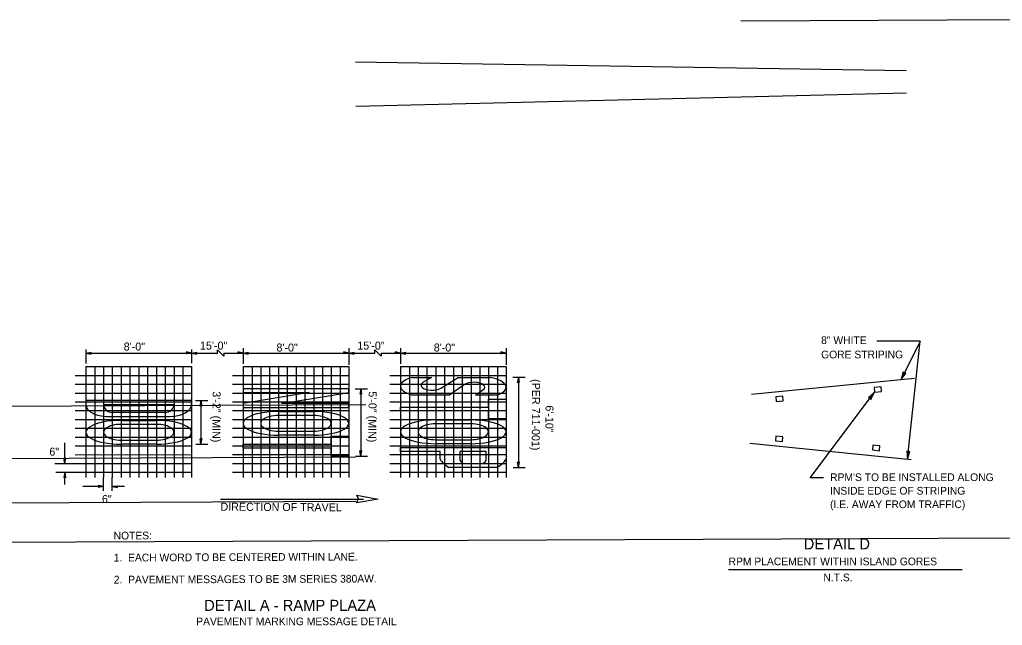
# Model space of a CAD drawing. Extents: x 583689 to 590775, y 1496016 to 1497365.
# Drawn here: x 587294 to 588186, y 1496787 to 1497337 of the extents above; entities that cross this region are included whole.
import ezdxf

# ---------------------------------------------------------------- set-up
doc = ezdxf.new("R2010")
doc.units = 0
for name, color, linetype in [('1', 7, 'Continuous'), ('12', 7, 'Continuous'), ('20', 7, 'Continuous'), ('21', 7, 'Continuous'), ('32', 7, 'Continuous'), ('5', 7, 'Continuous'), ('50', 7, 'Continuous'), ('52', 7, 'Continuous'), ('PavtMessage', 7, 'Continuous'), ('TextNotes', 7, 'Continuous')]:
    doc.layers.add(name, color=color, linetype=linetype)

msp = doc.modelspace()

# ---------------------------------------------------------------- linework, layer by layer
at = {"layer": '1'}
for points in [[(588075.82, 1497003.36), (588069.51, 1497002.74), (588069.93, 1496998.47), (588076.24, 1496999.09)], [(587986.62, 1496994.95), (587980.31, 1496994.33), (587980.73, 1496990.06), (587987.04, 1496990.68)], [(587986.66, 1496957.79), (587980.34, 1496958.42), (587979.91, 1496954.15), (587986.23, 1496953.52)], [(588074.73, 1496949.55), (588068.41, 1496950.18), (588067.98, 1496945.91), (588074.3, 1496945.28)]]:
    msp.add_lwpolyline(points, close=True, dxfattribs=at)
at = {"layer": '12'}
for p, q in [((588106.1, 1497011), (587958.1, 1496996.48)), ((587956.6, 1496952.04), (588103.15, 1496937.28))]:
    msp.add_line(p, q, dxfattribs=at)
at = {"layer": '20'}
for p, q in [((587599.7, 1496898.06), (587601.24, 1496901.44)), ((587619.12, 1496901.14), (587599.7, 1496898.06)), ((587599.82, 1496904.89), (587619.12, 1496901.14)), ((587601.24, 1496901.44), (587599.82, 1496904.89))]:
    msp.add_line(p, q, dxfattribs=at)
at = {"layer": '21'}
for p, q in [((587353.86, 1497037.2), (587353.86, 1497024.45)), ((587353.86, 1497034.01), (587358.71, 1497034.78)), ((587353.86, 1497034.01), (587358.51, 1497034.34)), ((587353.86, 1497034.01), (587449.86, 1497034.01)), ((587353.86, 1497034.01), (587358.68, 1497033.07)), ((587353.86, 1497034.01), (587358.5, 1497033.52)), ((587358.33, 1497033.93), (587358.71, 1497034.78)), ((587358.68, 1497033.07), (587358.33, 1497033.93)), ((587445.39, 1497034.09), (587445, 1497033.24)), ((587449.86, 1497034.01), (587445, 1497033.24)), ((587449.86, 1497034.01), (587445.03, 1497034.95)), ((587445.03, 1497034.95), (587445.39, 1497034.09)), ((587449.86, 1497034.01), (587445.21, 1497033.68)), ((587449.86, 1497034.01), (587445.22, 1497034.49)), ((587449.86, 1497037.2), (587449.86, 1497024.75)), ((587449.86, 1497034.01), (587454.71, 1497034.78)), ((587449.86, 1497034.01), (587454.51, 1497034.33)), ((587449.86, 1497034.01), (587454.68, 1497033.07)), ((587449.86, 1497034.01), (587454.5, 1497033.52)), ((587449.86, 1497034.01), (587473.28, 1497034.01)), ((587454.33, 1497033.93), (587454.71, 1497034.78)), ((587454.68, 1497033.07), (587454.33, 1497033.93)), ((587473.28, 1497034.01), (587473.27, 1497036.99)), ((587473.27, 1497036.99), (587479.04, 1497031.02)), ((587479.04, 1497034.01), (587479.04, 1497031.02)), ((587479.04, 1497034.01), (587496.7, 1497034.01)), ((587492.23, 1497034.09), (587491.84, 1497033.24)), ((587496.7, 1497034.01), (587491.84, 1497033.24)), ((587496.7, 1497034.01), (587491.87, 1497034.95)), ((587491.87, 1497034.95), (587492.23, 1497034.09)), ((587496.7, 1497034.01), (587492.05, 1497034.49)), ((587496.7, 1497034.01), (587492.05, 1497033.69)), ((587496.7, 1497038.33), (587496.69, 1497024.31)), ((587496.7, 1497034.01), (587501.55, 1497034.78)), ((587496.7, 1497034.01), (587501.35, 1497034.34)), ((587496.7, 1497034.01), (587592.45, 1497034.01)), ((587496.7, 1497034.01), (587501.52, 1497033.07)), ((587496.7, 1497034.01), (587501.34, 1497033.53)), ((587501.17, 1497033.93), (587501.55, 1497034.78)), ((587501.52, 1497033.07), (587501.17, 1497033.93)), ((587587.97, 1497034.09), (587587.59, 1497033.24)), ((587592.45, 1497034.01), (587587.59, 1497033.24)), ((587592.45, 1497034.01), (587587.62, 1497034.95)), ((587587.62, 1497034.95), (587587.97, 1497034.09)), ((587592.45, 1497034.01), (587587.79, 1497033.68)), ((587592.45, 1497034.01), (587587.8, 1497034.49)), ((587592.7, 1497038.34), (587592.7, 1497023.26)), ((587592.7, 1497035.72), (587592.7, 1497023.26)), ((587592.7, 1497034.01), (587597.55, 1497034.78)), ((587592.7, 1497034.01), (587597.34, 1497034.33)), ((587592.7, 1497034.01), (587616.12, 1497034.01)), ((587592.7, 1497034.01), (587597.52, 1497033.07)), ((587592.7, 1497034.01), (587597.34, 1497033.52)), ((587597.17, 1497033.93), (587597.55, 1497034.78)), ((587597.52, 1497033.07), (587597.17, 1497033.93)), ((587616.12, 1497034.01), (587616.11, 1497036.99)), ((587616.11, 1497036.99), (587621.88, 1497031.02)), ((587621.88, 1497034.01), (587621.88, 1497031.02)), ((587621.88, 1497034.01), (587639.53, 1497034.01)), ((587635.06, 1497034.09), (587634.68, 1497033.24)), ((587639.53, 1497034.01), (587634.68, 1497033.24)), ((587639.53, 1497034.01), (587634.71, 1497034.95)), ((587634.71, 1497034.95), (587635.06, 1497034.09)), ((587639.53, 1497034.01), (587634.88, 1497033.69)), ((587639.53, 1497034.01), (587634.89, 1497034.49)), ((587639.53, 1497038.33), (587639.53, 1497024.31)), ((587639.53, 1497034.01), (587644.39, 1497034.78)), ((587639.53, 1497034.01), (587644.19, 1497034.34)), ((587639.53, 1497034.01), (587735.28, 1497034.01)), ((587639.53, 1497034.01), (587644.36, 1497033.07)), ((587639.53, 1497034.01), (587644.18, 1497033.53)), ((587644.01, 1497033.93), (587644.39, 1497034.78)), ((587644.36, 1497033.07), (587644.01, 1497033.93)), ((587730.81, 1497034.09), (587730.43, 1497033.24)), ((587735.28, 1497034.01), (587730.43, 1497033.24)), ((587735.28, 1497034.01), (587730.46, 1497034.95)), ((587730.46, 1497034.95), (587730.81, 1497034.09)), ((587735.28, 1497034.01), (587730.63, 1497033.68)), ((587735.28, 1497034.01), (587730.64, 1497034.49)), ((587735.53, 1497038.34), (587735.53, 1497023.26)), ((587735.53, 1497035.72), (587735.53, 1497023.26)), ((587344.26, 1497013.66), (587449.86, 1497013.67)), ((587353.86, 1497021.66), (587449.86, 1497021.67)), ((587353.86, 1497021.67), (587353.86, 1496920.87)), ((587361.86, 1497021.67), (587361.86, 1496920.87)), ((587369.86, 1497021.67), (587369.86, 1496920.87)), ((587377.86, 1497021.67), (587377.86, 1496920.87)), ((587385.86, 1497021.67), (587385.86, 1496920.87)), ((587393.86, 1497021.67), (587393.86, 1496920.87)), ((587401.86, 1497021.67), (587401.86, 1496920.87)), ((587409.86, 1497021.67), (587409.86, 1496920.87)), ((587417.86, 1497021.67), (587417.86, 1496920.87)), ((587425.86, 1497021.67), (587425.86, 1496920.87)), ((587433.86, 1497021.67), (587433.86, 1496920.87)), ((587441.86, 1497021.67), (587441.86, 1496920.87)), ((587449.86, 1497021.67), (587449.86, 1496920.87)), ((587487.1, 1497013.67), (587592.7, 1497013.67)), ((587496.7, 1497021.67), (587592.7, 1497021.67)), ((587496.7, 1497021.67), (587496.7, 1496920.87)), ((587504.7, 1497021.67), (587504.7, 1496920.87)), ((587512.7, 1497021.67), (587512.7, 1496920.87)), ((587520.7, 1497021.67), (587520.7, 1496920.87)), ((587528.7, 1497021.67), (587528.7, 1496920.87)), ((587536.7, 1497021.67), (587536.7, 1496920.87)), ((587544.7, 1497021.67), (587544.7, 1496920.87)), ((587552.7, 1497021.67), (587552.7, 1496920.87)), ((587560.7, 1497021.67), (587560.7, 1496920.87)), ((587568.7, 1497021.67), (587568.7, 1496920.87)), ((587576.7, 1497021.67), (587576.7, 1496920.87)), ((587584.7, 1497021.67), (587584.7, 1496920.87)), ((587592.7, 1497021.67), (587592.7, 1496920.87)), ((587629.94, 1497013.67), (587735.53, 1497013.67)), ((587639.53, 1497021.67), (587735.53, 1497021.67)), ((587639.53, 1497021.67), (587639.53, 1496920.87)), ((587647.53, 1497021.67), (587647.53, 1496920.87)), ((587655.53, 1497021.67), (587655.53, 1496920.87)), ((587663.53, 1497021.67), (587663.53, 1496920.87)), ((587671.53, 1497021.67), (587671.53, 1496920.87)), ((587679.53, 1497021.67), (587679.53, 1496920.87)), ((587687.53, 1497021.67), (587687.53, 1496920.87)), ((587695.53, 1497021.67), (587695.53, 1496920.87)), ((587703.53, 1497021.67), (587703.53, 1496920.87)), ((587711.53, 1497021.67), (587711.53, 1496920.87)), ((587719.53, 1497021.67), (587719.53, 1496920.87)), ((587727.53, 1497021.67), (587727.53, 1496920.87)), ((587735.53, 1497021.67), (587735.53, 1496920.87)), ((587344.26, 1497005.66), (587449.86, 1497005.67)), ((587487.1, 1497005.67), (587592.7, 1497005.67)), ((587629.94, 1497005.67), (587735.53, 1497005.67)), ((587741.52, 1497012.07), (587752.73, 1497012.07)), ((587746.5, 1497012.07), (587745.56, 1497007.24)), ((587745.56, 1497007.24), (587746.42, 1497007.6)), ((587746.5, 1497012.07), (587746.02, 1497007.43)), ((587746.42, 1497007.6), (587747.27, 1497007.21)), ((587746.5, 1497012.07), (587746.5, 1496930.07)), ((587746.5, 1497012.07), (587747.27, 1497007.21)), ((587746.5, 1497012.07), (587746.83, 1497007.42)), ((587344.26, 1496997.66), (587449.86, 1496997.67)), ((587487.1, 1496997.67), (587592.7, 1496997.67)), ((587598.42, 1497001.6), (587609.63, 1497001.6)), ((587603.41, 1497001.61), (587602.47, 1496996.78)), ((587602.47, 1496996.78), (587603.33, 1496997.14)), ((587603.41, 1497001.61), (587602.92, 1496996.97)), ((587603.33, 1496997.14), (587604.18, 1496996.75)), ((587603.41, 1497001.61), (587604.18, 1496996.75)), ((587603.41, 1497001.61), (587603.73, 1496996.96)), ((587603.41, 1497001.61), (587603.41, 1496940.38)), ((587629.94, 1496997.67), (587735.53, 1496997.67)), ((587344.26, 1496989.66), (587449.86, 1496989.67)), ((587453.38, 1496990.8), (587464.59, 1496990.8)), ((587458.36, 1496990.78), (587457.43, 1496985.96)), ((587458.36, 1496990.78), (587457.88, 1496986.14)), ((587458.36, 1496990.78), (587459.13, 1496985.93)), ((587458.36, 1496990.78), (587458.69, 1496986.13)), ((587458.36, 1496990.78), (587458.36, 1496951.21)), ((587487.1, 1496989.67), (587592.7, 1496989.67)), ((587629.94, 1496989.67), (587735.53, 1496989.67)), ((587344.26, 1496981.66), (587449.86, 1496981.67)), ((587457.43, 1496985.96), (587458.29, 1496986.31)), ((587458.29, 1496986.31), (587459.13, 1496985.93)), ((587487.1, 1496981.67), (587592.7, 1496981.67)), ((587629.94, 1496981.67), (587735.53, 1496981.67)), ((587344.26, 1496973.66), (587449.86, 1496973.67)), ((587487.1, 1496973.67), (587592.7, 1496973.67)), ((587629.94, 1496973.67), (587735.53, 1496973.67)), ((587344.26, 1496965.66), (587449.86, 1496965.67)), ((587487.1, 1496965.67), (587592.7, 1496965.67)), ((587629.94, 1496965.67), (587735.53, 1496965.67)), ((587334.68, 1496933.66), (587334.68, 1496952.31)), ((587344.26, 1496957.66), (587449.86, 1496957.67)), ((587453.68, 1496951.2), (587464.58, 1496951.2)), ((587458.36, 1496951.21), (587457.59, 1496956.07)), ((587458.44, 1496955.68), (587457.59, 1496956.07)), ((587458.36, 1496951.21), (587458.04, 1496955.86)), ((587458.36, 1496951.21), (587459.3, 1496956.04)), ((587458.36, 1496951.21), (587458.85, 1496955.85)), ((587459.3, 1496956.04), (587458.44, 1496955.68)), ((587487.1, 1496957.67), (587592.7, 1496957.67)), ((587629.94, 1496957.67), (587735.54, 1496957.67)), ((587344.26, 1496949.66), (587449.86, 1496949.67)), ((587487.1, 1496949.67), (587592.7, 1496949.67)), ((587603.41, 1496940.38), (587602.64, 1496945.24)), ((587603.48, 1496944.85), (587602.64, 1496945.24)), ((587603.41, 1496940.38), (587603.08, 1496945.03)), ((587603.41, 1496940.38), (587604.34, 1496945.21)), ((587603.41, 1496940.38), (587603.89, 1496945.02)), ((587604.34, 1496945.21), (587603.48, 1496944.85)), ((587629.94, 1496949.67), (587735.54, 1496949.67)), ((587325.72, 1496933.66), (587344.26, 1496933.66)), ((587334.68, 1496933.66), (587333.91, 1496938.52)), ((587334.76, 1496938.13), (587333.91, 1496938.52)), ((587334.68, 1496933.66), (587334.35, 1496938.31)), ((587334.68, 1496933.66), (587335.61, 1496938.49)), ((587334.68, 1496933.66), (587335.16, 1496938.3)), ((587335.61, 1496938.49), (587334.76, 1496938.13)), ((587344.26, 1496941.66), (587449.86, 1496941.67)), ((587344.26, 1496933.66), (587449.86, 1496933.67)), ((587487.1, 1496941.67), (587592.7, 1496941.67)), ((587487.1, 1496933.67), (587592.7, 1496933.67)), ((587598.73, 1496940.38), (587609.63, 1496940.38)), ((587629.94, 1496941.67), (587735.54, 1496941.67)), ((587629.94, 1496933.67), (587735.54, 1496933.67)), ((587746.5, 1496930.07), (587745.73, 1496934.93)), ((587746.58, 1496934.54), (587745.73, 1496934.93)), ((587746.5, 1496930.07), (587746.17, 1496934.72)), ((587746.5, 1496930.07), (587747.44, 1496934.9)), ((587746.5, 1496930.07), (587746.99, 1496934.71)), ((587747.44, 1496934.9), (587746.58, 1496934.54)), ((587326.47, 1496925.62), (587344.26, 1496925.62)), ((587334.68, 1496925.62), (587333.74, 1496920.79)), ((587334.68, 1496925.62), (587334.19, 1496920.98)), ((587334.68, 1496914.43), (587334.68, 1496925.62)), ((587334.68, 1496925.62), (587335.45, 1496920.76)), ((587334.68, 1496925.62), (587335, 1496920.97)), ((587344.26, 1496925.66), (587449.86, 1496925.67)), ((587487.1, 1496925.67), (587592.7, 1496925.67)), ((587629.94, 1496925.67), (587735.54, 1496925.67)), ((587741.82, 1496930.06), (587752.73, 1496930.06)), ((587333.74, 1496920.79), (587334.6, 1496921.15)), ((587334.6, 1496921.15), (587335.45, 1496920.76)), ((587369.86, 1496908.82), (587369.86, 1496920.87)), ((587377.85, 1496908.82), (587377.86, 1496920.87)), ((587369.86, 1496912.66), (587351.21, 1496912.66)), ((587365.39, 1496912.74), (587365, 1496911.89)), ((587369.86, 1496912.66), (587365, 1496911.89)), ((587369.86, 1496912.66), (587365.03, 1496913.6)), ((587365.03, 1496913.6), (587365.39, 1496912.74)), ((587369.86, 1496912.66), (587365.21, 1496912.33)), ((587369.86, 1496912.66), (587365.22, 1496913.15)), ((587377.85, 1496912.66), (587382.71, 1496913.43)), ((587377.85, 1496912.66), (587382.5, 1496912.98)), ((587389.04, 1496912.66), (587377.85, 1496912.66)), ((587377.85, 1496912.66), (587382.68, 1496911.72)), ((587377.85, 1496912.66), (587382.49, 1496912.18)), ((587382.32, 1496912.59), (587382.71, 1496913.43)), ((587382.68, 1496911.72), (587382.32, 1496912.59)), ((587476.07, 1496901.29), (587606.06, 1496901.3))]:
    msp.add_line(p, q, dxfattribs=at)
at = {"layer": '5'}
for p, q in [((587948.53, 1497335.77), (588198.57, 1497336.88)), ((588098.73, 1497290.4), (587598.69, 1497298.22)), ((587598.86, 1497258.23), (588098.81, 1497270.47)), ((585969.09, 1496980.1), (587608.17, 1496987.35)), ((587598.69, 1496939.31), (583688.73, 1496922.03)), ((583688.9, 1496882.03), (587598.86, 1496899.31)), ((588199.06, 1496865.96), (586110.22, 1496856.73))]:
    msp.add_line(p, q, dxfattribs=at)
at = {"layer": '50'}
for p, q in [((588111.31, 1497044.79), (588072.15, 1497044.81)), ((588111.31, 1497044.79), (588093.99, 1497009.81)), ((588099.91, 1496937.6), (588111.31, 1497044.79)), ((588011.42, 1496920.49), (588069.93, 1496998.47)), ((588023.54, 1496920.49), (588011.42, 1496920.49)), ((587937.37, 1496837.41), (588149.42, 1496837.41))]:
    msp.add_line(p, q, dxfattribs=at)
at = {"layer": '52'}
for p, q in [((588096, 1497016.91), (588093.99, 1497009.81)), ((588093.99, 1497009.81), (588098.46, 1497015.69)), ((588096.96, 1497015.81), (588096, 1497016.91)), ((588098.46, 1497015.69), (588096.96, 1497015.81)), ((588069.93, 1496998.47), (588064.45, 1496993.51)), ((588066.65, 1496991.86), (588069.93, 1496998.47)), ((588064.45, 1496993.51), (588065.9, 1496993.11)), ((588065.9, 1496993.11), (588066.65, 1496991.86)), ((588100.62, 1496944.26), (588099.33, 1496944.95)), ((588099.33, 1496944.95), (588099.91, 1496937.6)), ((588099.91, 1496937.6), (588102.07, 1496944.66)), ((588102.07, 1496944.66), (588100.62, 1496944.26))]:
    msp.add_line(p, q, dxfattribs=at)
at = {"layer": 'PavtMessage'}
for p, q in [((587650.3, 1497011.92), (587667.76, 1497011.92)), ((587667.76, 1497011.92), (587660.19, 1497007.45)), ((587676.28, 1497002.12), (587691.72, 1497011.92)), ((587697.69, 1497005.37), (587683.87, 1496995.73)), ((587691.72, 1497011.92), (587721.05, 1497011.92)), ((587592.5, 1497001.61), (587496.64, 1497001.61)), ((587496.64, 1497001.61), (587496.64, 1496998.01)), ((587496.64, 1496998.01), (587556.55, 1496998.01)), ((587556.55, 1496998.01), (587496.64, 1496988.11)), ((587531.4, 1496988.11), (587592.5, 1496998.01)), ((587592.5, 1496998.01), (587592.5, 1497001.61)), ((587683.87, 1496995.73), (587650.3, 1496995.73)), ((587707.49, 1496995.73), (587714.41, 1497000.45)), ((587727.2, 1496995.73), (587707.49, 1496995.73)), ((587449.79, 1496990.78), (587353.93, 1496990.78)), ((587353.93, 1496990.78), (587353.93, 1496987.18)), ((587369.92, 1496987.18), (587433.83, 1496987.18)), ((587449.79, 1496987.18), (587449.79, 1496990.78)), ((587496.64, 1496988.11), (587496.64, 1496984.52)), ((587592.5, 1496988.11), (587531.4, 1496988.11)), ((587592.5, 1496984.52), (587592.5, 1496988.11)), ((587719.36, 1496992.13), (587735.34, 1496992.13)), ((587719.36, 1496984.94), (587719.36, 1496992.13)), ((587735.34, 1496992.13), (587735.34, 1496974.14)), ((587425.82, 1496979.99), (587377.89, 1496979.99)), ((587496.64, 1496984.52), (587592.5, 1496984.52)), ((587528.59, 1496980.92), (587560.55, 1496980.92)), ((587639.48, 1496981.34), (587639.48, 1496984.94)), ((587639.48, 1496984.94), (587719.36, 1496984.94)), ((587719.36, 1496981.34), (587639.48, 1496981.34)), ((587719.36, 1496974.14), (587719.36, 1496981.34)), ((587373.9, 1496976.39), (587429.82, 1496976.39)), ((587385.88, 1496972.79), (587417.84, 1496972.79)), ((587417.84, 1496969.2), (587385.88, 1496969.2)), ((587560.55, 1496977.32), (587528.59, 1496977.32)), ((587671.43, 1496973.24), (587703.39, 1496973.24)), ((587703.39, 1496969.64), (587671.43, 1496969.64)), ((587735.34, 1496974.14), (587719.36, 1496974.14)), ((587528.59, 1496962.93), (587560.55, 1496962.93)), ((587385.88, 1496954.8), (587417.84, 1496954.8)), ((587417.84, 1496951.21), (587385.88, 1496951.21)), ((587496.64, 1496947.58), (587496.64, 1496951.17)), ((587496.64, 1496951.17), (587576.53, 1496951.17)), ((587560.55, 1496959.33), (587528.59, 1496959.33)), ((587576.53, 1496958.37), (587592.5, 1496958.37)), ((587576.53, 1496951.17), (587576.53, 1496958.37)), ((587592.5, 1496958.37), (587592.5, 1496940.38)), ((587671.43, 1496955.25), (587703.39, 1496955.25)), ((587703.39, 1496951.65), (587671.43, 1496951.65)), ((587576.53, 1496947.58), (587496.64, 1496947.58)), ((587576.53, 1496940.38), (587576.53, 1496947.58)), ((587639.48, 1496948.06), (587735.34, 1496948.06)), ((587639.48, 1496944.46), (587639.48, 1496948.06)), ((587675.43, 1496944.46), (587639.48, 1496944.46)), ((587675.43, 1496937.57), (587675.43, 1496944.46)), ((587717.37, 1496944.46), (587693.4, 1496944.46)), ((587693.4, 1496944.46), (587693.4, 1496937.26)), ((587717.37, 1496937.26), (587717.37, 1496944.46)), ((587735.34, 1496948.06), (587735.34, 1496937.57)), ((587592.5, 1496940.38), (587576.53, 1496940.38)), ((587696.45, 1496933.67), (587714.32, 1496933.67)), ((587727.32, 1496930.07), (587683.45, 1496930.07))]:
    msp.add_line(p, q, dxfattribs=at)
for centre, major_axis, ratio, start_param, end_param in [((587671.43, 1497003.82), (-31.95, 0), 0.337782, 5.435123, 7.131247), ((587668.13, 1497004.72), (9.99, 0), 0.450376, 2.490106, 5.666015), ((587706.08, 1497002.92), (9.99, 0), 0.450376, 5.699287, 8.851109), ((587703.39, 1497002.92), (31.95, 0), 0.337782, 5.553458, 7.268296), ((587373.9, 1496987.18), (19.97, 0), 0.540451, 3.141593, 4.71335), ((587377.91, 1496987.18), (7.99, 0), 0.900751, 3.141593, 4.712389), ((587425.84, 1496987.18), (7.99, 0), 0.900751, 4.712389, 6.283185), ((587429.82, 1496987.18), (19.97, 0), 0.540451, 4.71335, 6.283185), ((587528.59, 1496970.12), (31.95, 0), 0.337782, 1.570796, 4.712389), ((587560.55, 1496970.12), (31.95, 0), 0.337782, 4.712389, 7.853982), ((587385.88, 1496962), (31.95, 0), 0.337782, 1.570796, 4.712389), ((587385.88, 1496962), (15.98, 0), 0.450376, 1.570796, 4.712389), ((587417.84, 1496962), (31.95, 0), 0.337782, 4.712389, 7.853982), ((587417.84, 1496962), (15.98, 0), 0.450376, 4.712389, 7.853982), ((587528.59, 1496970.12), (15.98, 0), 0.450376, 1.570796, 4.712389), ((587560.55, 1496970.12), (15.98, 0), 0.450376, 4.712389, 7.853982), ((587671.43, 1496962.45), (31.95, 0), 0.337782, 1.570796, 4.712389), ((587671.43, 1496962.45), (15.98, 0), 0.450376, 1.570796, 4.712389), ((587703.39, 1496962.45), (31.95, 0), 0.337782, 4.712389, 7.853982), ((587703.39, 1496962.45), (15.98, 0), 0.450376, 4.712389, 7.853982), ((587705.38, 1496944.46), (31.95, 0), 0.619266, 3.497014, 3.955933), ((587705.38, 1496937.26), (11.98, 0), 0.450376, 3.141593, 3.87132), ((587705.38, 1496937.26), (11.98, 0), 0.450376, 5.553458, 6.283185), ((587705.38, 1496944.46), (31.95, 0), 0.619266, 5.468845, 5.927764)]:
    msp.add_ellipse(centre, major_axis=major_axis, ratio=ratio, start_param=start_param, end_param=end_param, dxfattribs=at)

# ---------------------------------------------------------------- texts
at = {"layer": '20'}
for s, height, rotation, p in [(' 8\'-0"', 7.267, 359.70123, (587385.47, 1497036.31)), (' 15\'-0"', 7.267, 359.70123, (587454.76, 1497037.2)), (' 8\'-0"', 7.267, 359.70123, (587524.15, 1497035.41)), (' 15\'-0"', 7.267, 359.70123, (587597.6, 1497037.2)), (' 8\'-0"', 7.267, 359.70123, (587666.98, 1497035.41)), ('(PER 711-001)', 7.2669, 269.70123, (587758.97, 1497010.35)), ('3\'-2" (MIN)', 7.2669, 269.70123, (587468.93, 1496999.23)), ('5\'-0" (MIN)', 7.2669, 269.70123, (587610.57, 1496999.23)), ('6\'-10"', 7.267, 269.70123, (587771.2, 1496986.47)), ('6"', 7.267, 359.70123, (587320.65, 1496940.8)), ('6"', 7.267, 359.70123, (587368.38, 1496897.76)), ('DIRECTION OF TRAVEL', 7.2669, 359.70123, (587476.07, 1496890.76))]:
    msp.add_text(s, height=height, rotation=rotation, dxfattribs=at).set_placement(p)
at = {"layer": '32'}
for s, height, p in [('DETAIL A - RAMP PLAZA', 10, (587461.2, 1496799.78)), ('PAVEMENT MARKING MESSAGE DETAIL', 7, (587454.02, 1496786.69))]:
    msp.add_text(s, height=height, rotation=0.00473, dxfattribs=at).set_placement(p)
at = {"layer": '50'}
for s, height, p in [('8" WHITE', 7, (588021.44, 1497042.16)), ('GORE STRIPING', 7, (588021.44, 1497029.16)), ("RPM'S TO BE INSTALLED ALONG", 7, (588029.57, 1496917.67)), ('INSIDE EDGE OF STRIPING', 7, (588029.57, 1496905.39)), ('(I.E. AWAY FROM TRAFFIC)', 7, (588029.57, 1496893.11)), ('DETAIL D', 10, (588005.58, 1496855.62))]:
    msp.add_text(s, height=height, dxfattribs=at).set_placement(p)
for s, p in [('RPM PLACEMENT WITHIN ISLAND GORES', (587937.37, 1496841.17)), ('N.T.S.', (588023.48, 1496826.64))]:
    msp.add_text(s, height=7, rotation=359.99873, dxfattribs=at).set_placement(p)
at = {"layer": 'TextNotes'}
for s, p in [('NOTES:', (587379.03, 1496864.6)), ('1.  EACH WORD TO BE CENTERED WITHIN LANE.', (587379.11, 1496844.6)), ('2.  PAVEMENT MESSAGES TO BE 3M SERIES 380AW.', (587379.19, 1496824.61))]:
    msp.add_text(s, height=7, rotation=0.23586, dxfattribs=at).set_placement(p)

doc.saveas('drawing.dxf')
